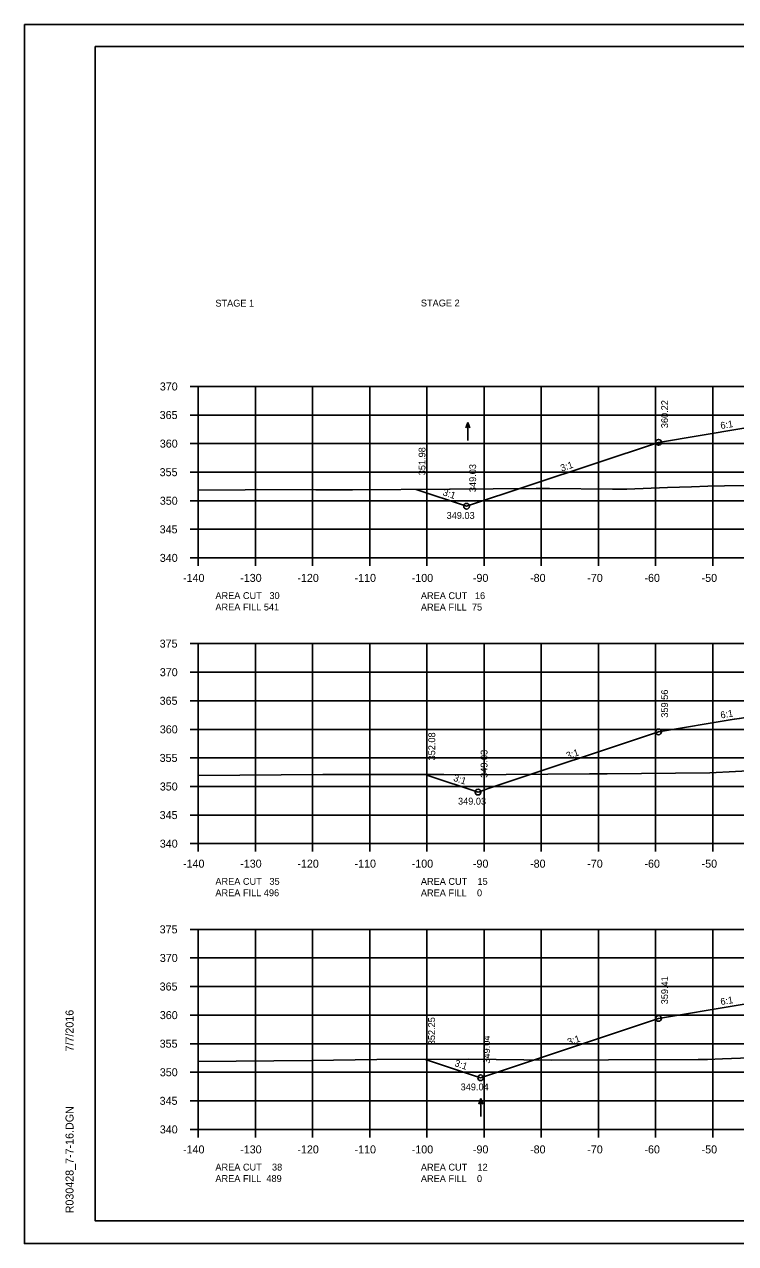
# Model space of a CAD drawing. Extents: x 1374859 to 1376773, y 382242 to 389804.
# Drawn here: x 1375964.2 to 1376088.6, y 385655.1 to 385868.5 of the extents above; entities that cross this region are included whole.
import ezdxf

# ---------------------------------------------------------------- set-up
doc = ezdxf.new("R2010")
doc.units = 0
for name, color, linetype in [('R_Axis', 7, 'Continuous'), ('R_Axis Annot', 7, 'Continuous'), ('R_Border', 7, 'Continuous'), ('R_Exist Surface', 7, 'Continuous'), ('R_Fin Surface', 7, 'Continuous'), ('R_Grid', 7, 'Continuous'), ('R_No Plot', 7, 'Continuous'), ('R_Water Annot', 7, 'Continuous'), ('R_Xsect Elev', 7, 'Continuous'), ('R_Xsect Slope', 7, 'Continuous')]:
    doc.layers.add(name, color=color, linetype=linetype)

msp = doc.modelspace()

# ---------------------------------------------------------------- linework, layer by layer
at = {"layer": 'R_Axis'}
for p, q in [((1375993.17, 385805.13), (1375994.57, 385805.13)), ((1375994.57, 385775.13), (1375994.57, 385805.13)), ((1375993.17, 385800.13), (1375994.57, 385800.13)), ((1375993.17, 385795.13), (1375994.57, 385795.13)), ((1375993.17, 385790.13), (1375994.57, 385790.13)), ((1375993.17, 385785.13), (1375994.57, 385785.13)), ((1375993.17, 385780.13), (1375994.57, 385780.13)), ((1375993.17, 385775.13), (1375994.57, 385775.13)), ((1375994.57, 385775.13), (1376274.57, 385775.13)), ((1375994.57, 385773.73), (1375994.57, 385775.13)), ((1376004.57, 385773.73), (1376004.57, 385775.13)), ((1376014.57, 385773.73), (1376014.57, 385775.13)), ((1376024.57, 385773.73), (1376024.57, 385775.13)), ((1376034.57, 385773.73), (1376034.57, 385775.13)), ((1376044.57, 385773.73), (1376044.57, 385775.13)), ((1376054.57, 385773.73), (1376054.57, 385775.13)), ((1376064.57, 385773.73), (1376064.57, 385775.13)), ((1376074.57, 385773.73), (1376074.57, 385775.13)), ((1376084.57, 385773.73), (1376084.57, 385775.13)), ((1375993.17, 385760.13), (1375994.57, 385760.13)), ((1375994.57, 385725.13), (1375994.57, 385760.13)), ((1375993.17, 385755.13), (1375994.57, 385755.13)), ((1375993.17, 385750.13), (1375994.57, 385750.13)), ((1375993.17, 385745.13), (1375994.57, 385745.13)), ((1375993.17, 385740.13), (1375994.57, 385740.13)), ((1375993.17, 385735.13), (1375994.57, 385735.13)), ((1375993.17, 385730.13), (1375994.57, 385730.13)), ((1375993.17, 385725.13), (1375994.57, 385725.13)), ((1375994.57, 385725.13), (1376274.57, 385725.13)), ((1375994.57, 385723.73), (1375994.57, 385725.13)), ((1376004.57, 385723.73), (1376004.57, 385725.13)), ((1376014.57, 385723.73), (1376014.57, 385725.13)), ((1376024.57, 385723.73), (1376024.57, 385725.13)), ((1376034.57, 385723.73), (1376034.57, 385725.13)), ((1376044.57, 385723.73), (1376044.57, 385725.13)), ((1376054.57, 385723.73), (1376054.57, 385725.13)), ((1376064.57, 385723.73), (1376064.57, 385725.13)), ((1376074.57, 385723.73), (1376074.57, 385725.13)), ((1376084.57, 385723.73), (1376084.57, 385725.13)), ((1375993.17, 385710.13), (1375994.57, 385710.13)), ((1375994.57, 385675.13), (1375994.57, 385710.13)), ((1375993.17, 385705.13), (1375994.57, 385705.13)), ((1375993.17, 385700.13), (1375994.57, 385700.13)), ((1375993.17, 385695.13), (1375994.57, 385695.13)), ((1375993.17, 385690.13), (1375994.57, 385690.13)), ((1375993.17, 385685.13), (1375994.57, 385685.13)), ((1375993.17, 385680.13), (1375994.57, 385680.13)), ((1375993.17, 385675.13), (1375994.57, 385675.13)), ((1375994.57, 385675.13), (1376274.57, 385675.13)), ((1375994.57, 385673.73), (1375994.57, 385675.13)), ((1376004.57, 385673.73), (1376004.57, 385675.13)), ((1376014.57, 385673.73), (1376014.57, 385675.13)), ((1376024.57, 385673.73), (1376024.57, 385675.13)), ((1376034.57, 385673.73), (1376034.57, 385675.13)), ((1376044.57, 385673.73), (1376044.57, 385675.13)), ((1376054.57, 385673.73), (1376054.57, 385675.13)), ((1376064.57, 385673.73), (1376064.57, 385675.13)), ((1376074.57, 385673.73), (1376074.57, 385675.13)), ((1376084.57, 385673.73), (1376084.57, 385675.13))]:
    msp.add_line(p, q, dxfattribs=at)
at = {"layer": 'R_Border'}
for p, q in [((1375976.57, 385864.59), (1376292.75, 385864.59)), ((1375976.57, 385659.13), (1375976.57, 385864.59)), ((1375976.57, 385659.13), (1375976.57, 385659.13)), ((1376292.75, 385659.13), (1375976.57, 385659.13))]:
    msp.add_line(p, q, dxfattribs=at)
at = {"layer": 'R_Exist Surface'}
for points in [[(1375994.57, 385786.99), (1376002.77, 385787.03), (1376004.96, 385787.07), (1376015.16, 385787.03), (1376021.53, 385787.02), (1376038.54, 385787.15), (1376038.55, 385787.15), (1376038.63, 385787.16), (1376053.65, 385787.28), (1376056.01, 385787.28), (1376067.02, 385787.17), (1376069.54, 385787.16), (1376076.66, 385787.42), (1376080.85, 385787.57), (1376083.69, 385787.68), (1376086.59, 385787.75), (1376091.73, 385787.82)], [(1375994.57, 385737.03), (1376016.34, 385737.22), (1376037.5, 385737.22), (1376041.11, 385737.2), (1376062.98, 385737.35), (1376065.67, 385737.37), (1376066.07, 385737.37), (1376084.05, 385737.52), (1376093.04, 385738.01)], [(1375994.57, 385687.04), (1376014.43, 385687.18), (1376025.79, 385687.34), (1376041.76, 385687.4), (1376056.42, 385687.27), (1376066.32, 385687.33), (1376082.03, 385687.39), (1376083.62, 385687.39), (1376086.27, 385687.48), (1376095.78, 385687.84)]]:
    msp.add_lwpolyline(points, dxfattribs=at)
at = {"layer": 'R_Fin Surface'}
for points in [[(1376032.66, 385787.11), (1376041.51, 385784.16), (1376075.09, 385795.35), (1376089.65, 385797.78), (1376097.09, 385799.02), (1376105.09, 385799.34), (1376134.59, 385799.93), (1376164.09, 385800.03), (1376172.09, 385800.06), (1376181.9, 385798.43), (1376194.09, 385796.4), (1376225.13, 385786.05), (1376229.47, 385787.49)], [(1376034.36, 385737.21), (1376034.92, 385737.02), (1376043.5, 385734.16), (1376045.48, 385734.82), (1376075.09, 385744.69), (1376088.33, 385746.9), (1376089.22, 385747.05), (1376096.63, 385748.28), (1376097.09, 385748.36), (1376097.57, 385748.38), (1376105.09, 385748.68), (1376106.89, 385748.71), (1376134.59, 385749.38), (1376162.29, 385750.06), (1376164.09, 385750.09), (1376164.57, 385750.1), (1376172.09, 385750.28), (1376172.74, 385750.17), (1376194.09, 385748.72)], [(1376034.32, 385687.38), (1376043.96, 385684.16), (1376075.09, 385694.54), (1376088.98, 385696.86), (1376097.09, 385698.21), (1376105.09, 385698.53), (1376134.59, 385699.3), (1376164.09, 385700.07), (1376172.09, 385700.28), (1376194.09, 385698.19)]]:
    msp.add_lwpolyline(points, dxfattribs=at)
at = {"layer": 'R_Grid'}
for p, q in [((1375994.57, 385805.13), (1376274.57, 385805.13)), ((1375994.57, 385775.13), (1375994.57, 385805.13)), ((1376004.57, 385775.13), (1376004.57, 385805.13)), ((1376014.57, 385775.13), (1376014.57, 385805.13)), ((1376024.57, 385775.13), (1376024.57, 385805.13)), ((1376034.57, 385775.13), (1376034.57, 385805.13)), ((1376044.57, 385775.13), (1376044.57, 385805.13)), ((1376054.57, 385775.13), (1376054.57, 385805.13)), ((1376064.57, 385775.13), (1376064.57, 385805.13)), ((1376074.57, 385775.13), (1376074.57, 385805.13)), ((1376084.57, 385775.13), (1376084.57, 385805.13)), ((1375994.57, 385800.13), (1376274.57, 385800.13)), ((1375994.57, 385795.13), (1376274.57, 385795.13)), ((1375994.57, 385790.13), (1376274.57, 385790.13)), ((1375994.57, 385785.13), (1376274.57, 385785.13)), ((1375994.57, 385780.13), (1376274.57, 385780.13)), ((1375994.57, 385775.13), (1376274.57, 385775.13)), ((1375994.57, 385760.13), (1376274.57, 385760.13)), ((1375994.57, 385725.13), (1375994.57, 385760.13)), ((1376004.57, 385725.13), (1376004.57, 385760.13)), ((1376014.57, 385725.13), (1376014.57, 385760.13)), ((1376024.57, 385725.13), (1376024.57, 385760.13)), ((1376034.57, 385725.13), (1376034.57, 385760.13)), ((1376044.57, 385725.13), (1376044.57, 385760.13)), ((1376054.57, 385725.13), (1376054.57, 385760.13)), ((1376064.57, 385725.13), (1376064.57, 385760.13)), ((1376074.57, 385725.13), (1376074.57, 385760.13)), ((1376084.57, 385725.13), (1376084.57, 385760.13)), ((1375994.57, 385755.13), (1376274.57, 385755.13)), ((1375994.57, 385750.13), (1376274.57, 385750.13)), ((1375994.57, 385745.13), (1376274.57, 385745.13)), ((1375994.57, 385740.13), (1376274.57, 385740.13)), ((1375994.57, 385735.13), (1376274.57, 385735.13)), ((1375994.57, 385730.13), (1376274.57, 385730.13)), ((1375994.57, 385725.13), (1376274.57, 385725.13)), ((1375994.57, 385710.13), (1376274.57, 385710.13)), ((1375994.57, 385675.13), (1375994.57, 385710.13)), ((1376004.57, 385675.13), (1376004.57, 385710.13)), ((1376014.57, 385675.13), (1376014.57, 385710.13)), ((1376024.57, 385675.13), (1376024.57, 385710.13)), ((1376034.57, 385675.13), (1376034.57, 385710.13)), ((1376044.57, 385675.13), (1376044.57, 385710.13)), ((1376054.57, 385675.13), (1376054.57, 385710.13)), ((1376064.57, 385675.13), (1376064.57, 385710.13)), ((1376074.57, 385675.13), (1376074.57, 385710.13)), ((1376084.57, 385675.13), (1376084.57, 385710.13)), ((1375994.57, 385705.13), (1376274.57, 385705.13)), ((1375994.57, 385700.13), (1376274.57, 385700.13)), ((1375994.57, 385695.13), (1376274.57, 385695.13)), ((1375994.57, 385690.13), (1376274.57, 385690.13)), ((1375994.57, 385685.13), (1376274.57, 385685.13)), ((1375994.57, 385680.13), (1376274.57, 385680.13)), ((1375994.57, 385675.13), (1376274.57, 385675.13))]:
    msp.add_line(p, q, dxfattribs=at)
at = {"layer": 'R_No Plot'}
for p, q in [((1375964.17, 385868.48), (1376297.5, 385868.48)), ((1375964.17, 385655.15), (1376297.5, 385655.15))]:
    msp.add_line(p, q, dxfattribs=at)
for points in [[(1375964.16, 385868.48), (1376297.5, 385868.48), (1376297.5, 385655.15), (1375964.16, 385655.15)], [(1376210.49, 385864.59), (1376210.49, 385854.71), (1376246.22, 385854.71), (1376246.22, 385851.79), (1376269.42, 385851.79), (1376269.42, 385827.46), (1376292.75, 385827.46), (1376292.75, 385659.13), (1375976.57, 385659.13), (1375976.57, 385864.59)]]:
    msp.add_lwpolyline(points, close=True, dxfattribs=at)
for centre in [(1376075.09, 385795.35), (1376041.51, 385784.16), (1376075.09, 385744.69), (1376043.5, 385734.16), (1376075.09, 385694.54), (1376043.96, 385684.16)]:
    msp.add_circle(centre, 0.5, dxfattribs=at)
at = {"layer": 'R_Water Annot'}
for p, q in [((1376041.71, 385798.82), (1376041.36, 385797.86)), ((1376041.71, 385795.68), (1376041.71, 385798.82)), ((1376041.71, 385798.82), (1376042.06, 385797.86)), ((1376044.01, 385680.53), (1376043.66, 385679.56)), ((1376044.01, 385677.38), (1376044.01, 385680.53)), ((1376044.01, 385680.53), (1376044.36, 385679.56))]:
    msp.add_line(p, q, dxfattribs=at)

# ---------------------------------------------------------------- texts
at = {"layer": 'R_Axis Annot'}
for s, p in [('STAGE 1', (1375997.57, 385819.1)), ('STAGE 2', (1376033.51, 385819.13))]:
    msp.add_text(s, height=1.2, rotation=360, dxfattribs=at).set_placement(p)
for s, height, p in [('370', 1.4, (1375987.85, 385804.43)), ('365', 1.4, (1375987.82, 385799.43)), ('360', 1.4, (1375987.85, 385794.43)), ('355', 1.4, (1375987.82, 385789.43)), ('350', 1.4, (1375987.85, 385784.43)), ('345', 1.4, (1375987.82, 385779.43)), ('340', 1.4, (1375987.85, 385774.43)), ('-140', 1.4, (1375991.91, 385770.93)), ('-130', 1.4, (1376001.91, 385770.93)), ('-120', 1.4, (1376011.91, 385770.93)), ('-110', 1.4, (1376021.91, 385770.93)), ('-100', 1.4, (1376031.91, 385770.93)), ('-90', 1.4, (1376042.61, 385770.93)), ('-80', 1.4, (1376052.61, 385770.93)), ('-70', 1.4, (1376062.61, 385770.93)), ('-60', 1.4, (1376072.61, 385770.93)), ('-50', 1.4, (1376082.61, 385770.93)), ('AREA CUT   30', 1.2, (1375997.57, 385767.93)), ('AREA CUT   16', 1.2, (1376033.51, 385767.92)), ('AREA FILL 541', 1.2, (1375997.57, 385765.93)), ('AREA FILL  75', 1.2, (1376033.51, 385765.92)), ('375', 1.4, (1375987.82, 385759.43)), ('370', 1.4, (1375987.85, 385754.43)), ('365', 1.4, (1375987.82, 385749.43)), ('360', 1.4, (1375987.85, 385744.43)), ('355', 1.4, (1375987.82, 385739.43)), ('350', 1.4, (1375987.85, 385734.43)), ('345', 1.4, (1375987.82, 385729.43)), ('340', 1.4, (1375987.85, 385724.43)), ('-140', 1.4, (1375991.91, 385720.93)), ('-130', 1.4, (1376001.91, 385720.93)), ('-120', 1.4, (1376011.91, 385720.93)), ('-110', 1.4, (1376021.91, 385720.93)), ('-100', 1.4, (1376031.91, 385720.93)), ('-90', 1.4, (1376042.61, 385720.93)), ('-80', 1.4, (1376052.61, 385720.93)), ('-70', 1.4, (1376062.61, 385720.93)), ('-60', 1.4, (1376072.61, 385720.93)), ('-50', 1.4, (1376082.61, 385720.93)), ('AREA CUT   35', 1.2, (1375997.57, 385717.93)), ('AREA CUT    15', 1.2, (1376033.51, 385717.92)), ('AREA FILL 496', 1.2, (1375997.57, 385715.93)), ('AREA FILL    0', 1.2, (1376033.51, 385715.92)), ('375', 1.4, (1375987.82, 385709.43)), ('370', 1.4, (1375987.85, 385704.43)), ('365', 1.4, (1375987.82, 385699.43)), ('360', 1.4, (1375987.85, 385694.43)), ('355', 1.4, (1375987.82, 385689.43)), ('350', 1.4, (1375987.85, 385684.43)), ('345', 1.4, (1375987.82, 385679.43)), ('340', 1.4, (1375987.85, 385674.43)), ('-140', 1.4, (1375991.91, 385670.93)), ('-130', 1.4, (1376001.91, 385670.93)), ('-120', 1.4, (1376011.91, 385670.93)), ('-110', 1.4, (1376021.91, 385670.93)), ('-100', 1.4, (1376031.91, 385670.93)), ('-90', 1.4, (1376042.61, 385670.93)), ('-80', 1.4, (1376052.61, 385670.93)), ('-70', 1.4, (1376062.61, 385670.93)), ('-60', 1.4, (1376072.61, 385670.93)), ('-50', 1.4, (1376082.61, 385670.93)), ('AREA CUT    38', 1.2, (1375997.57, 385667.93)), ('AREA CUT    12', 1.2, (1376033.51, 385667.92)), ('AREA FILL  489', 1.2, (1375997.57, 385665.93)), ('AREA FILL    0', 1.2, (1376033.51, 385665.92))]:
    msp.add_text(s, height=height, dxfattribs=at).set_placement(p)
at = {"layer": 'R_Border'}
for s, p in [('7/7/2016', (1375972.76, 385688.77)), ('R030428_7-7-16.DGN', (1375972.76, 385660.45))]:
    msp.add_text(s, height=1.4, rotation=90, dxfattribs=at).set_placement(p)
at = {"layer": 'R_Xsect Elev'}
for s, p in [('360.22', (1376076.74, 385797.83)), ('351.98', (1376034.31, 385789.59)), ('349.03', (1376043.17, 385786.64)), ('359.56', (1376076.74, 385747.17)), ('352.08', (1376036.02, 385739.69)), ('349.03', (1376045.16, 385736.64)), ('359.41', (1376076.74, 385697.02)), ('352.25', (1376035.98, 385689.86)), ('349.04', (1376045.61, 385686.64))]:
    msp.add_text(s, height=1.2, rotation=90, dxfattribs=at).set_placement(p)
for s, p in [('349.03', (1376038.01, 385781.96)), ('349.03', (1376040, 385731.96)), ('349.04', (1376040.46, 385681.96))]:
    msp.add_text(s, height=1.2, dxfattribs=at).set_placement(p)
at = {"layer": 'R_Xsect Slope'}
for s, rotation, p in [('6:1', 9.4642, (1376086, 385797.67)), ('3:1', 18.4349, (1376058.14, 385790.23)), ('3:1', 341.5651, (1376037.24, 385786.11)), ('6:1', 9.4642, (1376086, 385747.02)), ('3:1', 18.4349, (1376059.14, 385739.9)), ('3:1', 341.5651, (1376039.09, 385736.16)), ('6:1', 9.4642, (1376086, 385696.87)), ('3:1', 18.4349, (1376059.36, 385689.83)), ('3:1', 341.5651, (1376039.3, 385686.24))]:
    msp.add_text(s, height=1.2, rotation=rotation, dxfattribs=at).set_placement(p)

doc.saveas('drawing.dxf')
